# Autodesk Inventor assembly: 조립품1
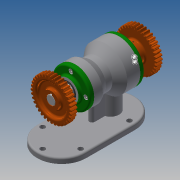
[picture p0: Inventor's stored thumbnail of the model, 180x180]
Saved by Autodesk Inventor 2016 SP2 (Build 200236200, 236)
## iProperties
Created: 2020-01
Part Number: 조립품1
Document SubType Name: Assembly
Designer: EZ
Author: EZ
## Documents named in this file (13)
- C:\Users\EZ\Desktop\ATC 자격시험\700104V1026\OldVersions\조립품1.iam
- C:\Users\EZ\Desktop\ATC 자격시험\700104V1026\모델링.ipt
- C:\Users\EZ\Desktop\ATC 자격시험\700104V1026\뒤커버.ipt
- C:\Users\EZ\Desktop\ATC 자격시험\700104V1026\멈춤나사 M3.ipt
- C:\Users\EZ\Desktop\ATC 자격시험\700104V1026\베어링 6203.ipt
- C:\Users\EZ\Desktop\ATC 자격시험\700104V1026\베어링 6205.ipt
- C:\Users\EZ\Desktop\ATC 자격시험\700104V1026\볼트 M4.ipt
- C:\Users\EZ\Desktop\ATC 자격시험\700104V1026\스퍼기어.ipt
- C:\Users\EZ\Desktop\ATC 자격시험\700104V1026\앞커버.ipt
- C:\Users\EZ\Desktop\ATC 자격시험\700104V1026\오일 실 17 30 8.ipt
- C:\Users\EZ\Desktop\ATC 자격시험\700104V1026\오일 실 25 38 8.ipt
- C:\Users\EZ\Desktop\ATC 자격시험\700104V1026\축.ipt
- C:\Users\EZ\Desktop\ATC 자격시험\700104V1026\키 5 x 5 x 18.ipt
